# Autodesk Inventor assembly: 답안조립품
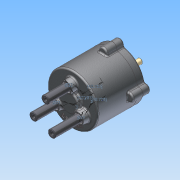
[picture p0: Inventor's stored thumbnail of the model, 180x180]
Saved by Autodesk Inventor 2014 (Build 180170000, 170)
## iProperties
Created: 2015-09
Part Number: 답안조립품
Document SubType Name: Assembly
Designer: study
Author: study
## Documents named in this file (14)
- C:\Users\study\Desktop\350916V1023\답안조립품.iam
- C:\Users\study\Desktop\350916V1023\몸체.ipt
- C:\Users\study\Desktop\350916V1023\커버.ipt
- C:\Users\study\Desktop\350916V1023\오일실.ipt
- C:\Users\study\Desktop\350916V1023\M5x0.8x20.ipt
- C:\Users\study\Desktop\350916V1023\메인 축.ipt
- C:\Users\study\Desktop\350916V1023\베어링 NA 4900.ipt
- C:\Users\study\Desktop\350916V1023\멈춤링 22 x 1.2.ipt
- C:\Users\study\Desktop\350916V1023\멈춤링 10 x 1.ipt
- C:\Users\study\Desktop\350916V1023\판캠.ipt
- C:\Users\study\Desktop\350916V1023\슬라이드 축.ipt
- C:\Users\study\Desktop\350916V1023\가변 스프링-01 [가변부품].ipt
- C:\Users\study\Desktop\350916V1023\가변 스프링-02 [가변부품].ipt
- C:\Users\study\Desktop\350916V1023\가변 스프링-03 [가변부품].ipt
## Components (7 placed, 4 different names)
1. 가변 스프링-01 [가변부품]:1
2. 가변 스프링-02 [가변부품]:1
3. 가변 스프링-03 [가변부품]:1
4. M5x0.8x20:1
5. M5x0.8x20:2
6. M5x0.8x20:3
7. M5x0.8x20:4
